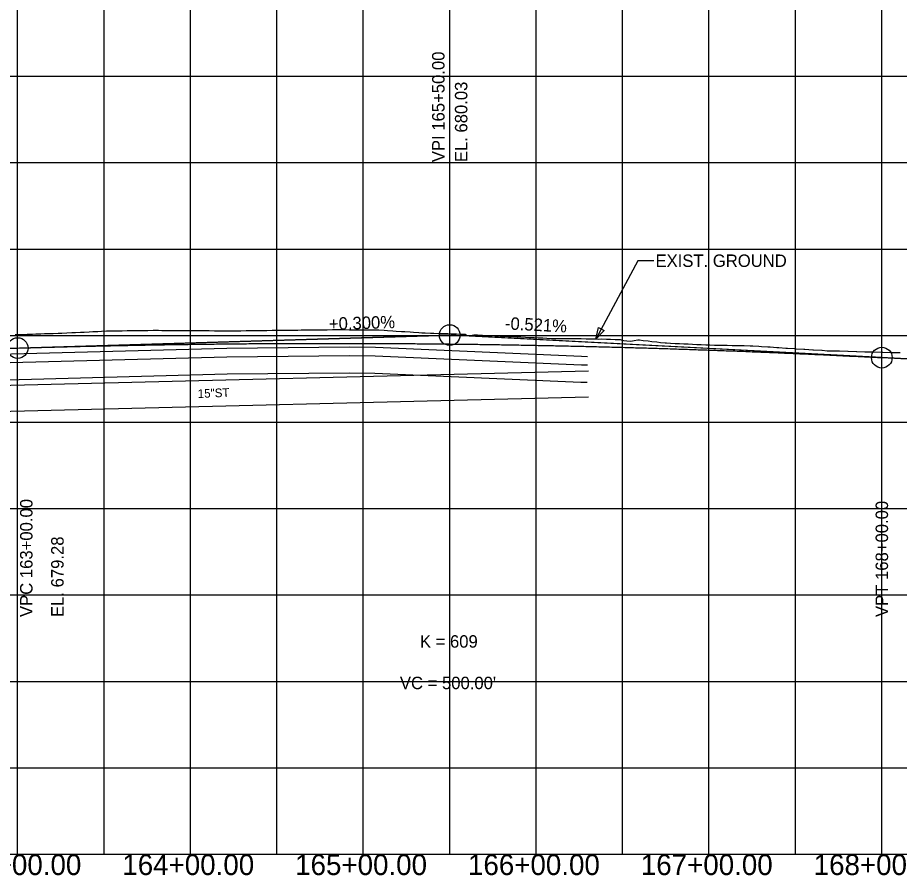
# Model space of a CAD drawing. Extents: x -7164 to 2214450, y -19642 to 253469.
# Drawn here: x 10300 to 10810, y -3012 to -2516 of the extents above; entities that cross this region are included whole.
import ezdxf

# ---------------------------------------------------------------- set-up
doc = ezdxf.new("R2010")
doc.units = 0
for name, color, linetype in [('DESIGN - PROFILE - Proposed', 7, 'Continuous'), ('DESIGN - PROFILE - Proposed Curve Text', 7, 'Continuous'), ('DESIGN - PROFILE - Proposed Text', 7, 'Continuous'), ('DESIGN - SCRATCH - User 1', 7, 'Continuous'), ('DESIGN - SCRATCH - User 2', 7, 'Continuous'), ('DESIGN - SHEET - Light Grid', 7, 'Continuous'), ('SURVEY - PROFILE - Drainage - Storm Sewer', 7, 'Continuous'), ('SURVEY - PROFILE - Drainage - Storm Sewer Text', 7, 'Continuous'), ('SURVEY - PROFILE - Ground Line with Text', 7, 'Continuous'), ('SURVEY - PROFILE - Utilities - Cable with Text', 7, 'Continuous'), ('SURVEY - PROFILE - Utilities - Electric with Text', 7, 'Continuous'), ('XTREE', 7, 'Continuous')]:
    doc.layers.add(name, color=color, linetype=linetype)

msp = doc.modelspace()

# ---------------------------------------------------------------- linework, layer by layer
at = {"layer": 'DESIGN - PROFILE - Proposed'}
for p, q in [((9500, -2731.23), (10300, -2707.23)), ((9500, -2731.23), (10300, -2707.23)), ((10800, -2712.77), (10960.7, -2721.15)), ((10800, -2712.77), (10960.7, -2721.15))]:
    msp.add_line(p, q, dxfattribs=at)
msp.add_spline([(10300, -2707.23), (10310, -2706.94), (10320, -2706.67), (10330, -2706.41), (10340, -2706.17), (10350, -2705.94), (10360, -2705.73), (10370, -2705.54), (10380, -2705.36), (10390, -2705.2), (10400, -2705.06), (10410, -2704.93), (10420, -2704.82), (10430, -2704.72), (10440, -2704.64), (10450, -2704.58), (10460, -2704.54), (10470, -2704.51), (10480, -2704.5), (10490, -2704.5), (10500, -2704.52), (10510, -2704.56), (10520, -2704.61), (10530, -2704.68), (10540, -2704.77), (10550, -2704.87), (10560, -2704.99), (10570, -2705.12), (10580, -2705.27), (10590, -2705.44), (10600, -2705.63), (10610, -2705.83), (10620, -2706.05), (10630, -2706.28), (10640, -2706.53), (10650, -2706.8), (10660, -2707.08), (10670, -2707.38), (10680, -2707.7), (10690, -2708.03), (10700, -2708.38), (10710, -2708.74), (10720, -2709.12), (10730, -2709.52), (10740, -2709.94), (10750, -2710.37), (10760, -2710.82), (10770, -2711.28), (10780, -2711.76), (10790, -2712.26), (10800, -2712.77)], degree=3, dxfattribs=at)
msp.add_spline([(10300, -2707.23), (10310, -2706.94), (10320, -2706.67), (10330, -2706.41), (10340, -2706.17), (10350, -2705.94), (10360, -2705.73), (10370, -2705.54), (10380, -2705.36), (10390, -2705.2), (10400, -2705.06), (10410, -2704.93), (10420, -2704.82), (10430, -2704.72), (10440, -2704.64), (10450, -2704.58), (10460, -2704.54), (10470, -2704.51), (10480, -2704.5), (10490, -2704.5), (10500, -2704.52), (10510, -2704.56), (10520, -2704.61), (10530, -2704.68), (10540, -2704.77), (10550, -2704.87), (10560, -2704.99), (10570, -2705.12), (10580, -2705.27), (10590, -2705.44), (10600, -2705.63), (10610, -2705.83), (10620, -2706.05), (10630, -2706.28), (10640, -2706.53), (10650, -2706.8), (10660, -2707.08), (10670, -2707.38), (10680, -2707.7), (10690, -2708.03), (10700, -2708.38), (10710, -2708.74), (10720, -2709.12), (10730, -2709.52), (10740, -2709.94), (10750, -2710.37), (10760, -2710.82), (10770, -2711.28), (10780, -2711.76), (10790, -2712.26), (10800, -2712.77)], degree=3, dxfattribs=at)
at = {"layer": 'DESIGN - PROFILE - Proposed Text'}
for p, q in [((10300, -2707.23), (10544, -2699.91)), ((10300, -2707.23), (10544, -2699.91)), ((10800, -2712.77), (10555.99, -2700.05)), ((10800, -2712.77), (10555.99, -2700.05))]:
    msp.add_line(p, q, dxfattribs=at)
msp.add_lwpolyline([(10668.04, -2656.72), (10658.86, -2656.72), (10634.49, -2702.18)], dxfattribs=at)
msp.add_lwpolyline([(10668.04, -2656.72), (10658.86, -2656.72), (10634.49, -2702.18)], dxfattribs=at)
msp.add_lwpolyline([(10639.28, -2697.08), (10634.49, -2702.18), (10636.08, -2695.36)], close=True, dxfattribs=at)
msp.add_lwpolyline([(10639.28, -2697.08), (10634.49, -2702.18), (10636.08, -2695.36)], close=True, dxfattribs=at)
for centre in [(10550, -2699.73), (10550, -2699.73), (10300, -2707.23), (10300, -2707.23), (10800, -2712.77), (10800, -2712.77)]:
    msp.add_circle(centre, 6, dxfattribs=at)
at = {"layer": 'DESIGN - SCRATCH - User 1'}
msp.add_line((0, -3000), (12400, -3000), dxfattribs=at)
msp.add_line((0, -3000), (12400, -3000), dxfattribs=at)
at = {"layer": 'DESIGN - SHEET - Light Grid'}
for p, q in [((10300, -3000), (10300, -1000)), ((10300, -3000), (10300, -1000)), ((10350, -3000), (10350, -1000)), ((10350, -3000), (10350, -1000)), ((10400, -3000), (10400, -1000)), ((10400, -3000), (10400, -1000)), ((10450, -3000), (10450, -1000)), ((10450, -3000), (10450, -1000)), ((10500, -3000), (10500, -1000)), ((10500, -3000), (10500, -1000)), ((10550, -3000), (10550, -1000)), ((10550, -3000), (10550, -1000)), ((10600, -3000), (10600, -1000)), ((10600, -3000), (10600, -1000)), ((10650, -3000), (10650, -1000)), ((10650, -3000), (10650, -1000)), ((10700, -3000), (10700, -1000)), ((10700, -3000), (10700, -1000)), ((10750, -3000), (10750, -1000)), ((10750, -3000), (10750, -1000)), ((10800, -3000), (10800, -1000)), ((10800, -3000), (10800, -1000)), ((0, -2550), (12400, -2550)), ((0, -2550), (12400, -2550)), ((0, -2600), (12400, -2600)), ((0, -2600), (12400, -2600)), ((0, -2650), (12400, -2650)), ((0, -2650), (12400, -2650)), ((0, -2700), (12400, -2700)), ((0, -2700), (12400, -2700)), ((0, -2750), (12400, -2750)), ((0, -2750), (12400, -2750)), ((0, -2800), (12400, -2800)), ((0, -2800), (12400, -2800)), ((0, -2850), (12400, -2850)), ((0, -2850), (12400, -2850)), ((0, -2900), (12400, -2900)), ((0, -2900), (12400, -2900)), ((0, -2950), (12400, -2950)), ((0, -2950), (12400, -2950)), ((-1000, -3000), (11000, -3000)), ((-1000, -3000), (11000, -3000))]:
    msp.add_line(p, q, dxfattribs=at)
at = {"layer": 'SURVEY - PROFILE - Drainage - Storm Sewer'}
for p, q in [((10203.93, -2731), (10630.33, -2720.39)), ((10203.93, -2731), (10630.33, -2720.39)), ((10203.93, -2746), (10630.33, -2735.39)), ((10203.93, -2746), (10630.33, -2735.39))]:
    msp.add_line(p, q, dxfattribs=at)
at = {"layer": 'SURVEY - PROFILE - Ground Line with Text'}
for points in [[(10298.51, -2699.38), (10301.41, -2699.34), (10303.51, -2699.33), (10305.59, -2699.27), (10308.51, -2699.15), (10310.59, -2699.09), (10313.51, -2698.97), (10315.58, -2698.9), (10318.51, -2698.79), (10320.56, -2698.72), (10323.51, -2698.6), (10325.53, -2698.53), (10328.51, -2698.4), (10331.45, -2698.26), (10333.46, -2698.19), (10336.45, -2698.04), (10338.46, -2697.97), (10341.45, -2697.82), (10343.46, -2697.74), (10346.47, -2697.59), (10348.46, -2697.51), (10351.49, -2697.36), (10353.44, -2697.28), (10355.4, -2697.27), (10358.44, -2697.22), (10360.4, -2697.21), (10363.44, -2697.16), (10365.39, -2697.14), (10368.44, -2697.09), (10370.37, -2697.07), (10373.44, -2697.02), (10375.35, -2697), (10378.44, -2696.94), (10381.43, -2696.97), (10383.34, -2696.98), (10386.41, -2697.01), (10388.34, -2697.02), (10391.4, -2697.04), (10393.34, -2697.05), (10396.4, -2697.07), (10398.34, -2697.07), (10401.4, -2697.09), (10403.29, -2697.1), (10403.87, -2697.1), (10405.81, -2697.11), (10408.87, -2697.14), (10410.81, -2697.15), (10413.87, -2697.18), (10415.81, -2697.19), (10418.87, -2697.21), (10420.8, -2697.22), (10423.88, -2697.24), (10424.24, -2697.24), (10427.21, -2697.19), (10429.13, -2697.19), (10432.2, -2697.14), (10434.13, -2697.14), (10437.19, -2697.08), (10439.13, -2697.08), (10442.2, -2697.02), (10444.13, -2697.02), (10447.21, -2696.96), (10449.13, -2696.95)], [(10298.51, -2699.38), (10301.41, -2699.34), (10303.51, -2699.33), (10305.59, -2699.27), (10308.51, -2699.15), (10310.59, -2699.09), (10313.51, -2698.97), (10315.58, -2698.9), (10318.51, -2698.79), (10320.56, -2698.72), (10323.51, -2698.6), (10325.53, -2698.53), (10328.51, -2698.4), (10331.45, -2698.26), (10333.46, -2698.19), (10336.45, -2698.04), (10338.46, -2697.97), (10341.45, -2697.82), (10343.46, -2697.74), (10346.47, -2697.59), (10348.46, -2697.51), (10351.49, -2697.36), (10353.44, -2697.28), (10355.4, -2697.27), (10358.44, -2697.22), (10360.4, -2697.21), (10363.44, -2697.16), (10365.39, -2697.14), (10368.44, -2697.09), (10370.37, -2697.07), (10373.44, -2697.02), (10375.35, -2697), (10378.44, -2696.94), (10381.43, -2696.97), (10383.34, -2696.98), (10386.41, -2697.01), (10388.34, -2697.02), (10391.4, -2697.04), (10393.34, -2697.05), (10396.4, -2697.07), (10398.34, -2697.07), (10401.4, -2697.09), (10403.29, -2697.1), (10403.87, -2697.1), (10405.81, -2697.11), (10408.87, -2697.14), (10410.81, -2697.15), (10413.87, -2697.18), (10415.81, -2697.19), (10418.87, -2697.21), (10420.8, -2697.22), (10423.88, -2697.24), (10424.24, -2697.24), (10427.21, -2697.19), (10429.13, -2697.19), (10432.2, -2697.14), (10434.13, -2697.14), (10437.19, -2697.08), (10439.13, -2697.08), (10442.2, -2697.02), (10444.13, -2697.02), (10447.21, -2696.96), (10449.13, -2696.95)], [(10449.13, -2696.95), (10452.23, -2696.88), (10454.13, -2696.88), (10457.27, -2696.81), (10459.06, -2696.8), (10462.13, -2696.8), (10464, -2696.76), (10467.1, -2696.75), (10469, -2696.71), (10472.08, -2696.7), (10474, -2696.66), (10477.08, -2696.65), (10479, -2696.6), (10482.08, -2696.59), (10483.97, -2696.54), (10487.02, -2696.56), (10488.96, -2696.59), (10492.01, -2696.6), (10493.96, -2696.63), (10497.01, -2696.65), (10498.96, -2696.68), (10502.02, -2696.69), (10503.96, -2696.71), (10507.03, -2696.72), (10508.95, -2696.75), (10512.03, -2696.95), (10513.95, -2697.07), (10517.03, -2697.28), (10518.95, -2697.4), (10522.04, -2697.6), (10523.95, -2697.72), (10527.06, -2697.91), (10528.95, -2698.03), (10532.09, -2698.23), (10533.94, -2698.34), (10535.8, -2698.4), (10538.94, -2698.53), (10540.84, -2698.59), (10543.94, -2698.72), (10545.87, -2698.78), (10548.94, -2698.9), (10550.89, -2698.96), (10553.94, -2699.07), (10555.9, -2699.13), (10558.94, -2699.24), (10560.09, -2699.92), (10561.75, -2700.01), (10563.94, -2699.5), (10566, -2699.62), (10568.94, -2699.76), (10571.04, -2699.88), (10573.94, -2700.02), (10576.08, -2700.14), (10578.94, -2700.27), (10581.11, -2700.39), (10583.94, -2700.52), (10586.13, -2700.59), (10588.93, -2700.75), (10591.15, -2700.82), (10593.93, -2700.97), (10596.17, -2701.04), (10598.93, -2701.19), (10601.18, -2701.25), (10603.93, -2701.4), (10606.18, -2701.46), (10608.92, -2701.61), (10611.18, -2701.62), (10613.92, -2701.67), (10616.18, -2701.68), (10618.92, -2701.73), (10621.16, -2701.74), (10623.92, -2701.78), (10626.14, -2701.79), (10628.92, -2701.84), (10631.1, -2701.84), (10633.92, -2701.89), (10635.81, -2702), (10637.97, -2701.97), (10640.79, -2702.13), (10642.98, -2702.1), (10645.78, -2702.25), (10647.16, -2702.23), (10647.24, -2702.23), (10648.64, -2702.34), (10650.47, -2702.87), (10652.39, -2703.11), (10654.85, -2703.2), (10656.63, -2702.91), (10658.9, -2702.41), (10659.75, -2702.47), (10661.99, -2702.85), (10664.74, -2703.03), (10667, -2703.42), (10669.73, -2703.61), (10672.01, -2703.99), (10674.73, -2704.18), (10675.44, -2704.3), (10677.78, -2704.41), (10680.44, -2704.52), (10682.86, -2704.63), (10685.44, -2704.74)], [(10449.13, -2696.95), (10452.23, -2696.88), (10454.13, -2696.88), (10457.27, -2696.81), (10459.06, -2696.8), (10462.13, -2696.8), (10464, -2696.76), (10467.1, -2696.75), (10469, -2696.71), (10472.08, -2696.7), (10474, -2696.66), (10477.08, -2696.65), (10479, -2696.6), (10482.08, -2696.59), (10483.97, -2696.54), (10487.02, -2696.56), (10488.96, -2696.59), (10492.01, -2696.6), (10493.96, -2696.63), (10497.01, -2696.65), (10498.96, -2696.68), (10502.02, -2696.69), (10503.96, -2696.71), (10507.03, -2696.72), (10508.95, -2696.75), (10512.03, -2696.95), (10513.95, -2697.07), (10517.03, -2697.28), (10518.95, -2697.4), (10522.04, -2697.6), (10523.95, -2697.72), (10527.06, -2697.91), (10528.95, -2698.03), (10532.09, -2698.23), (10533.94, -2698.34), (10535.8, -2698.4), (10538.94, -2698.53), (10540.84, -2698.59), (10543.94, -2698.72), (10545.87, -2698.78), (10548.94, -2698.9), (10550.89, -2698.96), (10553.94, -2699.07), (10555.9, -2699.13), (10558.94, -2699.24), (10560.09, -2699.92), (10561.75, -2700.01), (10563.94, -2699.5), (10566, -2699.62), (10568.94, -2699.76), (10571.04, -2699.88), (10573.94, -2700.02), (10576.08, -2700.14), (10578.94, -2700.27), (10581.11, -2700.39), (10583.94, -2700.52), (10586.13, -2700.59), (10588.93, -2700.75), (10591.15, -2700.82), (10593.93, -2700.97), (10596.17, -2701.04), (10598.93, -2701.19), (10601.18, -2701.25), (10603.93, -2701.4), (10606.18, -2701.46), (10608.92, -2701.61), (10611.18, -2701.62), (10613.92, -2701.67), (10616.18, -2701.68), (10618.92, -2701.73), (10621.16, -2701.74), (10623.92, -2701.78), (10626.14, -2701.79), (10628.92, -2701.84), (10631.1, -2701.84), (10633.92, -2701.89), (10635.81, -2702), (10637.97, -2701.97), (10640.79, -2702.13), (10642.98, -2702.1), (10645.78, -2702.25), (10647.16, -2702.23), (10647.24, -2702.23), (10648.64, -2702.34), (10650.47, -2702.87), (10652.39, -2703.11), (10654.85, -2703.2), (10656.63, -2702.91), (10658.9, -2702.41), (10659.75, -2702.47), (10661.99, -2702.85), (10664.74, -2703.03), (10667, -2703.42), (10669.73, -2703.61), (10672.01, -2703.99), (10674.73, -2704.18), (10675.44, -2704.3), (10677.78, -2704.41), (10680.44, -2704.52), (10682.86, -2704.63), (10685.44, -2704.74)], [(10685.44, -2704.74), (10687.94, -2704.85), (10690.44, -2704.96), (10693.02, -2705.08), (10695.44, -2705.18), (10698.1, -2705.3), (10700.43, -2705.4), (10703.22, -2705.48), (10705.44, -2705.51), (10708.35, -2705.59), (10710.44, -2705.61), (10713.48, -2705.69), (10715.44, -2705.72), (10718.61, -2705.81), (10720.44, -2705.83), (10723.74, -2705.93), (10725.44, -2705.95), (10725.45, -2705.95), (10728.9, -2706.21), (10730.44, -2706.24), (10734.07, -2706.52), (10735.44, -2706.55), (10739.23, -2706.85), (10740.44, -2706.88), (10744.4, -2707.2), (10745.44, -2707.22), (10749.57, -2707.56), (10750.44, -2707.59), (10750.45, -2707.59), (10754.81, -2707.87), (10755.45, -2707.89), (10760.05, -2708.19), (10760.44, -2708.21), (10765.29, -2708.53), (10765.44, -2708.54), (10768.39, -2708.74), (10770.42, -2708.78), (10770.44, -2708.78), (10775.38, -2708.88), (10775.46, -2708.88), (10775.47, -2708.88), (10780.35, -2709.02), (10780.49, -2709.03), (10785.3, -2709.17), (10785.51, -2709.18), (10790.26, -2709.32), (10790.52, -2709.33), (10795.21, -2709.47), (10795.54, -2709.48), (10800.17, -2709.62), (10800.55, -2709.63), (10800.58, -2709.63), (10805.16, -2709.73), (10805.59, -2709.75), (10810.13, -2709.85), (10810.61, -2709.86)], [(10685.44, -2704.74), (10687.94, -2704.85), (10690.44, -2704.96), (10693.02, -2705.08), (10695.44, -2705.18), (10698.1, -2705.3), (10700.43, -2705.4), (10703.22, -2705.48), (10705.44, -2705.51), (10708.35, -2705.59), (10710.44, -2705.61), (10713.48, -2705.69), (10715.44, -2705.72), (10718.61, -2705.81), (10720.44, -2705.83), (10723.74, -2705.93), (10725.44, -2705.95), (10725.45, -2705.95), (10728.9, -2706.21), (10730.44, -2706.24), (10734.07, -2706.52), (10735.44, -2706.55), (10739.23, -2706.85), (10740.44, -2706.88), (10744.4, -2707.2), (10745.44, -2707.22), (10749.57, -2707.56), (10750.44, -2707.59), (10750.45, -2707.59), (10754.81, -2707.87), (10755.45, -2707.89), (10760.05, -2708.19), (10760.44, -2708.21), (10765.29, -2708.53), (10765.44, -2708.54), (10768.39, -2708.74), (10770.42, -2708.78), (10770.44, -2708.78), (10775.38, -2708.88), (10775.46, -2708.88), (10775.47, -2708.88), (10780.35, -2709.02), (10780.49, -2709.03), (10785.3, -2709.17), (10785.51, -2709.18), (10790.26, -2709.32), (10790.52, -2709.33), (10795.21, -2709.47), (10795.54, -2709.48), (10800.17, -2709.62), (10800.55, -2709.63), (10800.58, -2709.63), (10805.16, -2709.73), (10805.59, -2709.75), (10810.13, -2709.85), (10810.61, -2709.86)]]:
    msp.add_lwpolyline(points, dxfattribs=at)
at = {"layer": 'SURVEY - PROFILE - Utilities - Cable with Text'}
msp.add_lwpolyline([(10145.12, -2729.57), (10421.24, -2722.22), (10492.02, -2721.61), (10506.63, -2721.72), (10625.86, -2726.95), (10629.46, -2727.02)], dxfattribs=at)
msp.add_lwpolyline([(10145.12, -2729.57), (10421.24, -2722.22), (10492.02, -2721.61), (10506.63, -2721.72), (10625.86, -2726.95), (10629.46, -2727.02)], dxfattribs=at)
at = {"layer": 'SURVEY - PROFILE - Utilities - Electric with Text'}
for points in [[(3997.6, -2274.92), (4802.81, -2301.21), (4934.88, -2309.56), (5070.99, -2328.73), (5217.26, -2360.35), (5368.56, -2406.53), (5568.13, -2485.11), (5666.84, -2519.04), (5822.95, -2554.52), (6139.14, -2596.4), (6627.68, -2644.16), (7125.46, -2666.48), (7800.57, -2696.44), (8331.81, -2711.63), (8778.4, -2728.74), (9263.22, -2741.41), (9422.06, -2741.78), (9638.89, -2735.54), (10010.38, -2723.15), (10421.06, -2712.22), (10492.02, -2711.61), (10506.89, -2711.72), (10626.17, -2716.95), (10629.65, -2717.02)], [(3997.6, -2274.92), (4802.81, -2301.21), (4934.88, -2309.56), (5070.99, -2328.73), (5217.26, -2360.35), (5368.56, -2406.53), (5568.13, -2485.11), (5666.84, -2519.04), (5822.95, -2554.52), (6139.14, -2596.4), (6627.68, -2644.16), (7125.46, -2666.48), (7800.57, -2696.44), (8331.81, -2711.63), (8778.4, -2728.74), (9263.22, -2741.41), (9422.06, -2741.78), (9638.89, -2735.54), (10010.38, -2723.15), (10421.06, -2712.22), (10492.02, -2711.61), (10506.89, -2711.72), (10626.17, -2716.95), (10629.65, -2717.02)], [(9651.66, -2730.11), (10010.23, -2718.15), (10420.97, -2707.22), (10492.02, -2706.6), (10507.02, -2706.72), (10626.33, -2711.96), (10629.74, -2712.02)], [(9651.66, -2730.11), (10010.23, -2718.15), (10420.97, -2707.22), (10492.02, -2706.6), (10507.02, -2706.72), (10626.33, -2711.96), (10629.74, -2712.02)]]:
    msp.add_lwpolyline(points, dxfattribs=at)
at = {"layer": 'XTREE'}
for p, q in [((10550, -2699.73), (9300, -2737.23)), ((10550, -2699.73), (9300, -2737.23)), ((10960.7, -2721.15), (10550, -2699.73)), ((10960.7, -2721.15), (10550, -2699.73))]:
    msp.add_line(p, q, dxfattribs=at)

# ---------------------------------------------------------------- texts
at = {"layer": 'DESIGN - PROFILE - Proposed Curve Text'}
for s, p in [('VPI 165+50.00', (10547, -2599.73)), ('VPI 165+50.00', (10547, -2599.73)), ('EL. 680.03', (10560.2, -2599.73)), ('EL. 680.03', (10560.2, -2599.73))]:
    msp.add_text(s, height=7.2, rotation=90, dxfattribs=at).set_placement(p)
for s, p in [('K = 609', (10532.75, -2880.5)), ('K = 609', (10532.75, -2880.5)), ("VC = 500.00'", (10521.18, -2904.5)), ("VC = 500.00'", (10521.18, -2904.5))]:
    msp.add_text(s, height=7.2, dxfattribs=at).set_placement(p)
at = {"layer": 'DESIGN - PROFILE - Proposed Text'}
msp.add_text('EXIST. GROUND', height=7.2, dxfattribs=at).set_placement((10669.04, -2660.32))
msp.add_text('EXIST. GROUND', height=7.2, dxfattribs=at).set_placement((10669.04, -2660.32))
for s, rotation, p in [('+0.300%', 1.7184, (10480.2, -2696.83)), ('+0.300%', 1.7184, (10480.2, -2696.83)), ('-0.521%', 357.0151, (10581.8, -2696.39)), ('-0.521%', 357.0151, (10581.8, -2696.39)), ('VPC 163+00.00 ', 90, (10308.6, -2862.77)), ('VPC 163+00.00 ', 90, (10308.6, -2862.77)), ('VPT 168+00.00 ', 90, (10803.6, -2862.77)), ('VPT 168+00.00 ', 90, (10803.6, -2862.77)), ('EL. 679.28', 90, (10326.6, -2862.77)), ('EL. 679.28', 90, (10326.6, -2862.77))]:
    msp.add_text(s, height=7.2, rotation=rotation, dxfattribs=at).set_placement(p)
at = {"layer": 'DESIGN - SCRATCH - User 2'}
for s, p in [('163+00.00', (10260.56, -3012)), ('164+00.00', (10360.56, -3012)), ('165+00.00', (10460.56, -3012)), ('166+00.00', (10560.56, -3012)), ('167+00.00', (10660.56, -3012)), ('168+00.00', (10760.56, -3012))]:
    msp.add_text(s, height=12, dxfattribs=at).set_placement(p)
at = {"layer": 'SURVEY - PROFILE - Drainage - Storm Sewer Text'}
msp.add_text('15"ST', height=5, rotation=2.3061, dxfattribs=at).set_placement((10404.3, -2736.12))
msp.add_text('15"ST', height=5, rotation=2.3061, dxfattribs=at).set_placement((10404.3, -2736.12))

doc.saveas('drawing.dxf')
